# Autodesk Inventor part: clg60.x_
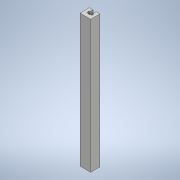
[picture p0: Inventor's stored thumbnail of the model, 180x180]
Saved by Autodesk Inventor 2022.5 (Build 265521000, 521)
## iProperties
Part Number: clg60.x_
Material: 一般
Document SubType Name: Modeling
Designer: ImaoCorp
Density: 1 g/cm^3
Appearance: 既定
Sending System: SOLIDWORKS 2017-2017317
MC: AMD64
MC_MODEL: Intel64 Family 6 Model 60 Stepping 3, GenuineIntel
OS: Windows_NT
FRU: Parasolid Version 29.0, build 201,  4-17-2017
FORMAT: text
GUISE: transmit
KEY: clg60
FILE: clg60.x_t
DATE: Mon Dec 17 11:37:55 2018
Author: ImaoCorp
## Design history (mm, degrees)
feature "Base1"
node "ソリッド1"
